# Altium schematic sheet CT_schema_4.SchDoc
size 287 x 160 mm
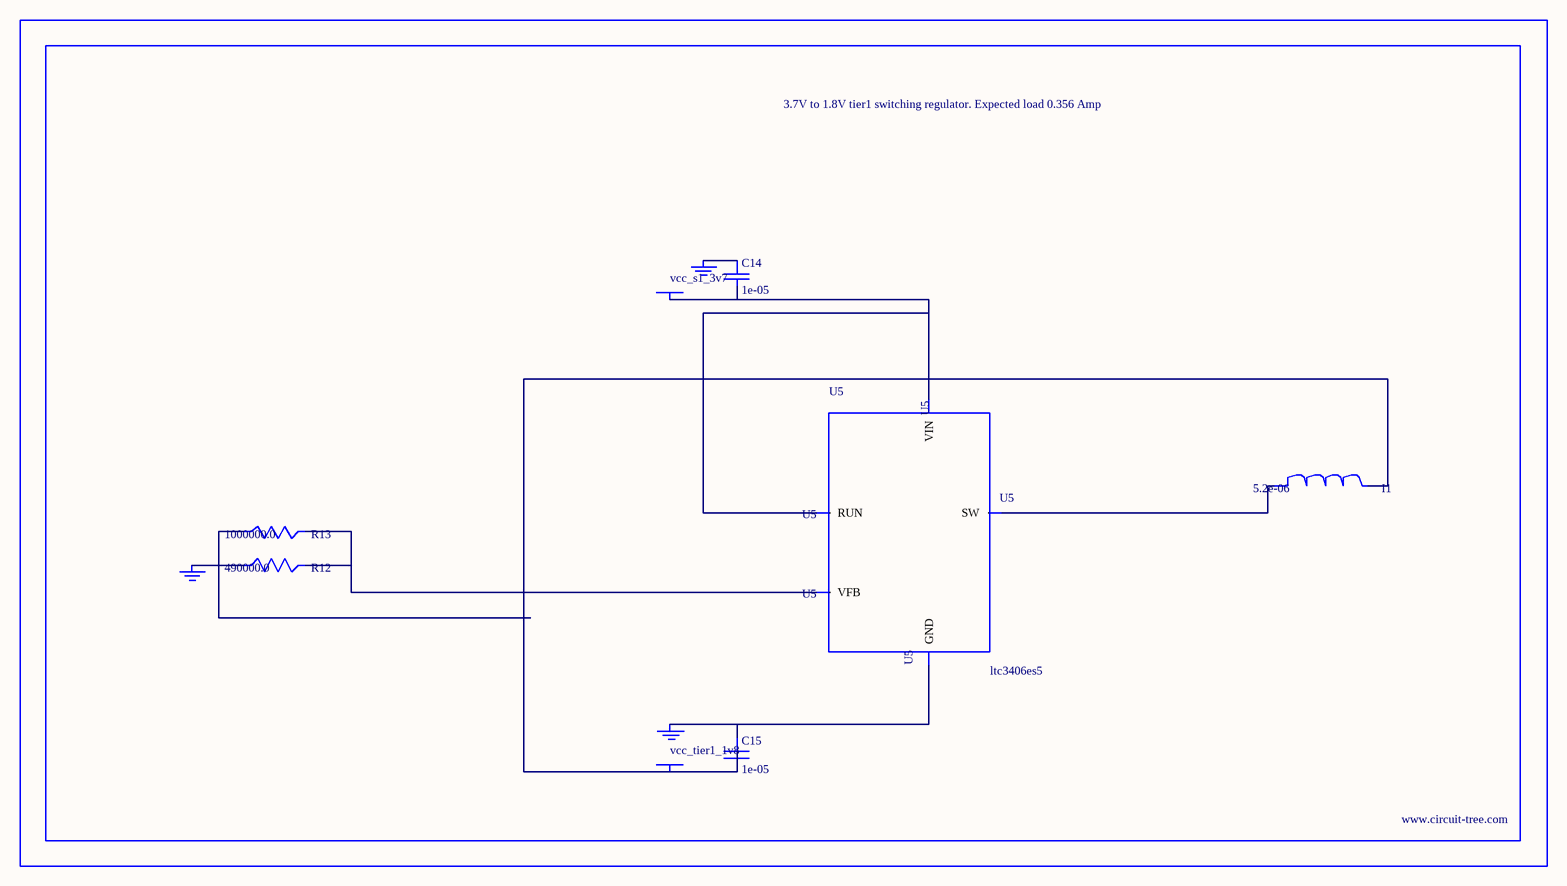
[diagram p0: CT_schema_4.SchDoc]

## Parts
BORDER3  (no value)
C14  1e-05  [C0805]
C15  1e-05  [C0805]
GND_INSTANCE_3_0  (no value)
GND_INSTANCE_3_1  (no value)
GND_INSTANCE_3_2  (no value)
I1  5.2e-06  [DR1040]
POWER_INSTANCE_3_0  vcc_tier1_1v8
POWER_INSTANCE_3_1  vcc_s1_3v7
R12  490000.0  [R0603]
R13  1000000.0  [R0603]
U5  ltc3406es5  [TSOT-23-5]

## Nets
NetC14_1: C14.1 GND_INSTANCE_3_1.0(GND)
NetC14_2: C14.2 POWER_INSTANCE_3_1.0(PWR) U5.1(RUN) U5.4(VIN)
NetC15_1: C15.1 GND_INSTANCE_3_0.0(GND) U5.2(GND)
NetC15_2: C15.2 I1.2 POWER_INSTANCE_3_0.0(PWR) R13.1
NetGND_INSTANCE_3_2_0: GND_INSTANCE_3_2.0(GND) R12.1
NetI1_1: I1.1 U5.3(SW)
NetR12_2: R12.2 R13.2 U5.5(VFB)

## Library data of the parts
BORDER3 = BORDER_PAGE3
C14 C15 = C0805C106K8RACTU
GND_INSTANCE_3_0-GND_INSTANCE_3_2 = GND
I1 = DR1040-5R2-R
POWER_INSTANCE_3_0 POWER_INSTANCE_3_1 = PWR
R12 = R12
R13 = RC0603JR-071ML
